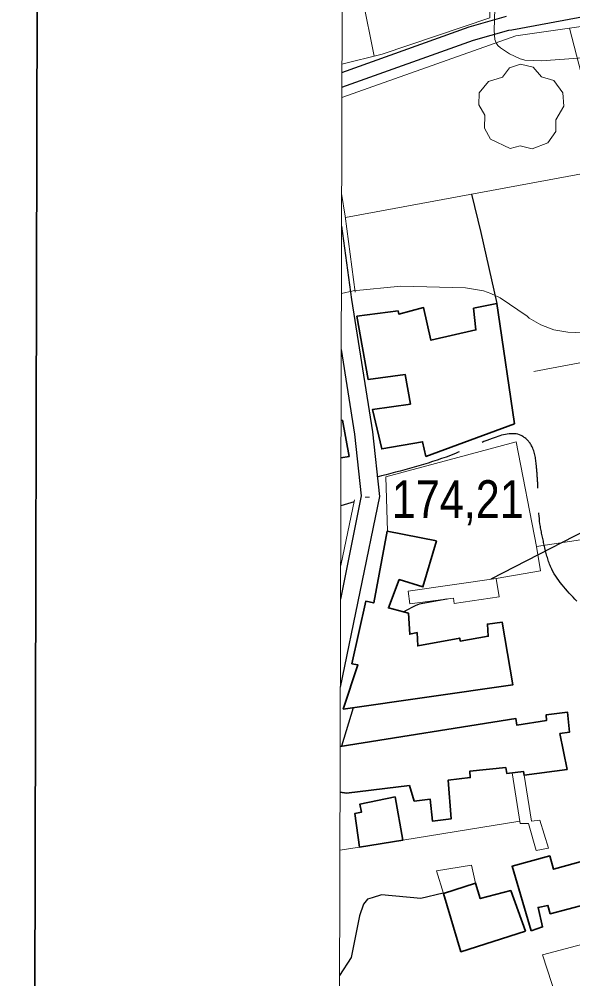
# Model space of a CAD drawing. Extents: x 480269 to 484877, y 4383588 to 4386804.
# Drawn here: x 480452.9 to 480580.6, y 4385573.2 to 4385794.6 of the extents above; entities that cross this region are included whole.
import ezdxf

# ---------------------------------------------------------------- set-up
doc = ezdxf.new("R2010")
doc.units = 0
doc.header["$LTSCALE"] = 3.8
doc.linetypes.add('LONG_DASHED', pattern=[7.5, 6, -1.5])
for name, color, linetype, lineweight in [('1', 7, 'Continuous', 13), ('25', 7, 'LONG_DASHED', 25), ('29', 7, 'Continuous', 13), ('36', 7, 'Continuous', 25), ('38', 7, 'Continuous', 25), ('47', 7, 'Continuous', 35), ('51', 7, 'Continuous', 13), ('7', 7, 'Continuous', 13), ('8', 7, 'Continuous', 25), ('9', 7, 'Continuous', 13)]:
    doc.layers.add(name, color=color, linetype=linetype, lineweight=lineweight)

msp = doc.modelspace()

# ---------------------------------------------------------------- linework, layer by layer
at = {"layer": '1', "lineweight": 35}
msp.add_lwpolyline([(480458.83, 4386528.21), (484176.23, 4386519.28), (484170.33, 4384064.28), (480452.93, 4384073.22)], close=True, dxfattribs=at)
at = {"layer": '1'}
msp.add_lwpolyline([(480529.1, 4386456.6), (484105.5, 4386448.1), (484100.5, 4384135.8), (480523.1, 4384144.4)], close=True, dxfattribs=at)
at = {"layer": '25'}
msp.add_line((480530.17, 4385683.28), (480527.09, 4385682.36), dxfattribs=at)
msp.add_lwpolyline([(480557.19, 4385754.24), (480559.4, 4385745.4), (480563.06, 4385729)], dxfattribs=at)
at = {"layer": '29'}
msp.add_lwpolyline([(480566.17, 4385764.82), (480561.63, 4385766.94), (480560.22, 4385769.48), (480560.32, 4385772.46), (480558.95, 4385774.87), (480558.99, 4385777.62), (480561.15, 4385780.22), (480564.34, 4385781.22), (480565.99, 4385783.41), (480568.56, 4385784.24), (480571.42, 4385783.59), (480573.37, 4385781.32), (480576.18, 4385780.5), (480578.31, 4385777.65), (480578.55, 4385774.52), (480576.67, 4385771.37), (480576.67, 4385768.69), (480574.85, 4385766.08), (480571.23, 4385764.74), (480568.46, 4385765.37)], close=True, dxfattribs=at)
at = {"layer": '36'}
for points in [[(480527.34, 4385778.91), (480557.71, 4385789.75), (480565.81, 4385792.13), (480566.54, 4385792.17), (480634.29, 4385804.84)], [(480527.35, 4385782.36), (480556.71, 4385792.84), (480565.26, 4385795.35)], [(480527.26, 4385746.88), (480529.56, 4385729.92), (480534.4, 4385699.44), (480536, 4385684.47), (480526.98, 4385640.49)], [(480527.18, 4385718.41), (480530.22, 4385698.89), (480531.75, 4385684.68), (480527.04, 4385660.82), (480527.03, 4385660.8)]]:
    msp.add_lwpolyline(points, dxfattribs=at)
at = {"layer": '38'}
msp.add_lwpolyline([(480550.73, 4385592.95), (480545.58, 4385591.75), (480536.5, 4385592.61), (480534.32, 4385591.9), (480533.27, 4385591.56), (480532.34, 4385590.42), (480531.37, 4385587.78), (480529.45, 4385578.16), (480526.81, 4385573.99)], dxfattribs=at)
at = {"layer": '38', "linetype": 'LONG_DASHED'}
msp.add_spline([(480581.52, 4385660.35), (480575.47, 4385668.31), (480574.01, 4385673.25), (480573.02, 4385678.22), (480572.49, 4385687.71), (480572.22, 4385691.28), (480571.08, 4385696.22), (480568.68, 4385698.57), (480562.03, 4385697.91), (480552.36, 4385693.99), (480535.36, 4385688.96)], degree=3, dxfattribs=at)
at = {"layer": '47'}
msp.add_line((480527.14, 4385702.07), (480527.46, 4385702.13), dxfattribs=at)
for points in [[(480530.82, 4385726.11), (480533.43, 4385711.48), (480541.9, 4385712.65), (480543.15, 4385705.82), (480534.39, 4385704.57), (480536.53, 4385695.47), (480545.96, 4385697.13), (480546.72, 4385693.73), (480567.12, 4385701.3), (480563.36, 4385726.96), (480563.06, 4385729), (480557.71, 4385727.93), (480558.24, 4385722.95), (480547.85, 4385720.53), (480546.19, 4385728.09), (480540.45, 4385726.57), (480540.3, 4385727.3)], [(480549.12, 4385674.25), (480537.77, 4385676.47), (480534.67, 4385659.95), (480532.85, 4385660.34), (480529.67, 4385645.91), (480531.04, 4385645.64), (480527.64, 4385635.43), (480566.75, 4385641.02), (480564.32, 4385655.5), (480560.9, 4385655.07), (480561.07, 4385652.25), (480554.64, 4385651.13), (480554.53, 4385651.84), (480544.82, 4385650.01), (480544.66, 4385653.08), (480543, 4385652.71), (480542.68, 4385657.55), (480538.07, 4385658.8), (480540.55, 4385665.34), (480546.02, 4385663.64)], [(480539.61, 4385615.2), (480541.41, 4385605.22), (480531.4, 4385603.61), (480530.35, 4385611.36), (480531.86, 4385611.66), (480531.48, 4385613.52)], [(480571.01, 4385584.29), (480566.57, 4385599.17), (480575.26, 4385601.57), (480576.16, 4385598.51), (480585.93, 4385601.21), (480588.69, 4385593.57), (480583.24, 4385592.27), (480583.49, 4385590.39), (480575.37, 4385588.24), (480574.85, 4385590.14), (480572.58, 4385589.7), (480573.61, 4385585.17)], [(480569.7, 4385584.17), (480566.29, 4385593.59), (480559.25, 4385591.74), (480558.16, 4385595.26), (480550.75, 4385592.89), (480554.8, 4385579.46)]]:
    msp.add_lwpolyline(points, close=True, dxfattribs=at)
for points in [[(480527.46, 4385702.13), (480529.01, 4385693.75), (480527.12, 4385693.4)], [(480526.95, 4385626.85), (480567.46, 4385633.26), (480567.65, 4385631.77), (480574.51, 4385632.8), (480574.46, 4385634.13), (480579.4, 4385634.7), (480579.79, 4385630.09), (480577.63, 4385629.8), (480579.26, 4385621.53), (480569.37, 4385620.17), (480569.21, 4385621.05), (480565.34, 4385620.6), (480565.13, 4385621.96), (480556.87, 4385621.14), (480556.94, 4385619.65), (480551.83, 4385619.01), (480552.52, 4385610.09), (480548.21, 4385609.6), (480547.71, 4385614.65), (480544.02, 4385614.24), (480542.9, 4385617.81), (480528.38, 4385616.06), (480526.92, 4385616.28)]]:
    msp.add_lwpolyline(points, dxfattribs=at)
at = {"layer": '47', "lineweight": 13}
msp.add_lwpolyline([(480542.64, 4385662.66), (480562.95, 4385665.58), (480563.58, 4385661.35), (480553.23, 4385659.8), (480553.06, 4385661.04), (480543.01, 4385659.7)], close=True, dxfattribs=at)
for points in [[(480566.58, 4385620.75), (480568.43, 4385609.02), (480570.4, 4385609.06), (480572.1, 4385602.8), (480575.01, 4385603.38), (480573, 4385609.85), (480571.07, 4385609.6), (480569.37, 4385620.17)], [(480558.16, 4385595.26), (480557.21, 4385599.44), (480549.13, 4385598.16), (480550.75, 4385592.89)]]:
    msp.add_lwpolyline(points, dxfattribs=at)
at = {"layer": '51'}
for p, q in [((480527.45, 4385822.26), (480534.78, 4385786.08)), ((480527.06, 4385668.54), (480530.27, 4385683.72)), ((480568.34, 4385609.56), (480541.41, 4385605.22)), ((480526.88, 4385602.88), (480531.4, 4385603.61))]:
    msp.add_line(p, q, dxfattribs=at)
for points in [[(480561.27, 4385858.85), (480561.43, 4385794.96), (480536.62, 4385786.52), (480527.36, 4385784.28)], [(480527.34, 4385776.59), (480567.42, 4385790.78), (480592.2, 4385794.32), (480658.53, 4385807.06), (480680.6, 4385811.47), (480687.26, 4385767.03), (480690.66, 4385736.36)], [(480528.15, 4385748.88), (480592.55, 4385760.76), (480582.53, 4385782.14), (480579.8, 4385792.55)], [(480530.39, 4385731.66), (480528.1, 4385749.17), (480527.28, 4385754.39)], [(480571.59, 4385713.35), (480607.08, 4385720.06), (480606.32, 4385726.9)], [(480537.84, 4385676.46), (480537.47, 4385689.05), (480567.49, 4385697.14), (480572.19, 4385672.96), (480587.41, 4385675.29), (480605.69, 4385670.43), (480607.92, 4385664.69)], [(480562.95, 4385665.58), (480573.14, 4385667.36), (480572.19, 4385672.96)], [(480576.8, 4385568.79), (480573.57, 4385578.76), (480584.07, 4385581.54), (480587.23, 4385572.81)]]:
    msp.add_lwpolyline(points, dxfattribs=at)
at = {"layer": '7'}
msp.add_line((480532.73, 4385684.32), (480533.73, 4385684.32), dxfattribs=at)
at = {"layer": '8'}
for p, q in [((480551.59, 4385660.84), (480551.57, 4385660.84)), ((480551.62, 4385660.85), (480551.59, 4385660.84)), ((480529.96, 4385635.76), (480527.23, 4385626.9))]:
    msp.add_line(p, q, dxfattribs=at)
for points in [[(480759.4, 4385664.1), (480753.99, 4385670.18), (480751.09, 4385672.23), (480745.34, 4385675.04), (480744.4, 4385675.28), (480743.27, 4385675.82), (480735.27, 4385682.17), (480735.27, 4385682.21), (480735.26, 4385682.22), (480735.25, 4385682.24), (480716.45, 4385687.77), (480712.87, 4385688.3), (480696.26, 4385687.72), (480692.81, 4385688.3), (480691.42, 4385688.96), (480672.98, 4385702.08), (480669.91, 4385702.89), (480666.77, 4385702.76), (480647.47, 4385698.78), (480625.53, 4385697.54), (480621.94, 4385696.45), (480561.65, 4385665.39)], [(480551.57, 4385660.84), (480545.15, 4385659.63), (480544.22, 4385659.29), (480541.87, 4385658.02), (480541.7, 4385657.82)]]:
    msp.add_lwpolyline(points, dxfattribs=at)
at = {"layer": '9'}
for points in [[(480599.72, 4385786.95), (480573.39, 4385785.05), (480569.55, 4385785.2), (480568.74, 4385785.39), (480568.48, 4385785.48), (480566.02, 4385786.63), (480563.89, 4385788.02), (480563.33, 4385788.58), (480563, 4385789.05), (480562.92, 4385789.2), (480562.59, 4385789.95), (480562.44, 4385791.99), (480563.08, 4385812.38)], [(480605.16, 4385729.88), (480591.39, 4385722.97), (480589.75, 4385722.52), (480586.14, 4385722.09), (480579.43, 4385722.43), (480576.24, 4385722.96), (480573.18, 4385724.08), (480570.56, 4385725.67), (480570.06, 4385726.07), (480563.81, 4385730.34), (480561.71, 4385731.37), (480559.99, 4385731.93), (480555.87, 4385732.65), (480540.93, 4385733), (480529.92, 4385731.95), (480527.22, 4385731.35)]]:
    msp.add_lwpolyline(points, dxfattribs=at)

# ---------------------------------------------------------------- texts
at = {"layer": '7', "width": 0.85}
msp.add_text('174,21', height=8.75, dxfattribs=at).set_placement((480538.85, 4385679.5))

doc.saveas('drawing.dxf')
